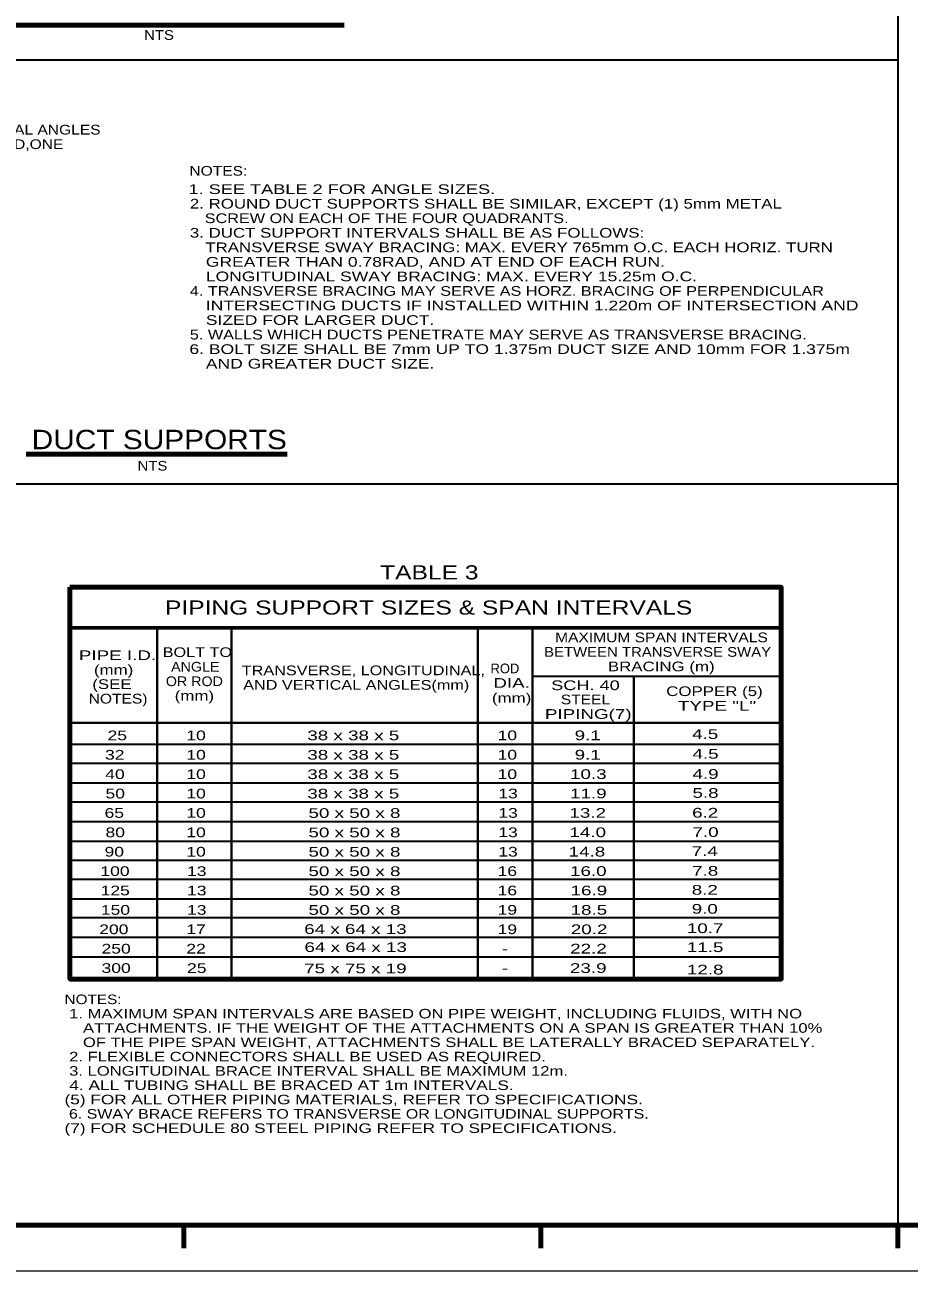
# Model space of a CAD drawing. Extents: x 55 to 190, y 198 to 264.
# Drawn here: x 117.13 to 140.29, y 198.45 to 231.1 of the extents above; entities that cross this region are included whole.
import ezdxf
from ezdxf.enums import TextEntityAlignment as Align

# ---------------------------------------------------------------- set-up
doc = ezdxf.new("R2010")
doc.units = 0
doc.header["$LTSCALE"] = 0.1
doc.layers.add('1', color=7, linetype='Continuous', lineweight=25)
doc.layers.add('2', color=7, linetype='Continuous', lineweight=40)

msp = doc.modelspace()

# ---------------------------------------------------------------- linework, layer by layer
at = {"layer": '1', "lineweight": 80}
for p, q in [((121.2927, 199.6512), (121.2927, 199.0512)), ((130.6427, 199.6512), (130.6427, 199.0512)), ((139.9927, 199.6512), (139.9927, 199.0512))]:
    msp.add_line(p, q, dxfattribs=at)
at = {"layer": '1', "lineweight": 13}
msp.add_lwpolyline([(62.4915, 257.8525), (146.5927, 257.8525), (146.5927, 198.4512), (62.4915, 198.4512)], close=True, dxfattribs=at)
at = {"layer": '1', "lineweight": 80}
msp.add_lwpolyline([(65.1915, 256.6525), (145.3927, 256.6525), (145.3927, 199.6512), (65.1915, 199.6512)], close=True, dxfattribs=at)
at = {"layer": '2', "lineweight": 35}
for p, q in [((139.9927, 256.6525), (139.9927, 199.6512)), ((102.5927, 230.1829), (139.9927, 230.1829)), ((102.5927, 219.0748), (139.9927, 219.0748)), ((130.4385, 214.0378), (136.9398, 214.0378)), ((118.3081, 212.2552), (136.9398, 212.2552)), ((118.3081, 211.753), (136.9398, 211.753)), ((118.3081, 211.2432), (136.9398, 211.2432)), ((118.3081, 210.741), (136.9398, 210.741)), ((118.3081, 210.2309), (136.9398, 210.2309)), ((118.3081, 209.7131), (136.9398, 209.7131)), ((118.3081, 209.2186), (136.9398, 209.2186)), ((118.3081, 208.7164), (136.9398, 208.7164)), ((118.3081, 208.1994), (136.9398, 208.1994)), ((118.3081, 207.7102), (136.9398, 207.7102)), ((118.3081, 207.1966), (136.9398, 207.1966)), ((118.3081, 206.6828), (136.9398, 206.6828))]:
    msp.add_line(p, q, dxfattribs=at)
at = {"layer": '2', "lineweight": 80}
for p, q in [((116.0467, 231.0941), (125.4958, 231.0941)), ((117.1647, 219.8485), (123.9978, 219.8485))]:
    msp.add_line(p, q, dxfattribs=at)
at = {"layer": '2', "lineweight": 60}
msp.add_line((136.9398, 215.3006), (118.3081, 215.3006), dxfattribs=at)
at = {"layer": '2'}
for p, q in [((120.5989, 215.3006), (120.5989, 206.092)), ((122.5412, 215.3006), (122.5393, 206.0923)), ((128.9946, 215.3006), (128.9946, 206.092)), ((130.4295, 215.3006), (130.4295, 206.0992)), ((133.078, 214.0378), (133.078, 206.0992)), ((118.3081, 212.8135), (136.9398, 212.8135))]:
    msp.add_line(p, q, dxfattribs=at)
at = {"layer": '2', "lineweight": 80}
msp.add_lwpolyline([(118.3081, 216.3645), (136.9398, 216.3645), (136.9398, 206.0992), (118.3081, 206.0992)], close=True, dxfattribs=at)

# ---------------------------------------------------------------- texts
at = {"layer": '1'}
for s, width, p in [('NOTES:', 1.2, (118.1687, 205.445)), (' 1. MAXIMUM SPAN INTERVALS ARE BASED ON PIPE WEIGHT, INCLUDING FLUIDS, WITH NO', 1.3, (118.1687, 205.07)), ('    ATTACHMENTS. IF THE WEIGHT OF THE ATTACHMENTS ON A SPAN IS GREATER THAN 10%', 1.3, (118.1687, 204.695)), ('    OF THE PIPE SPAN WEIGHT, ATTACHMENTS SHALL BE LATERALLY BRACED SEPARATELY.', 1.3, (118.1687, 204.32)), (' 2. FLEXIBLE CONNECTORS SHALL BE USED AS REQUIRED.', 1.3, (118.1687, 203.945)), (' 3. LONGITUDINAL BRACE INTERVAL SHALL BE MAXIMUM 12m.', 1.3, (118.1687, 203.57)), (' 4. ALL TUBING SHALL BE BRACED AT 1m INTERVALS.', 1.35, (118.1687, 203.195)), ('(5) FOR ALL OTHER PIPING MATERIALS, REFER TO SPECIFICATIONS.', 1.35, (118.1687, 202.82)), (' 6. SWAY BRACE REFERS TO TRANSVERSE OR LONGITUDINAL SUPPORTS.', 1.25, (118.1687, 202.445)), ('(7) FOR SCHEDULE 80 STEEL PIPING REFER TO SPECIFICATIONS.', 1.35, (118.1687, 202.07))]:
    msp.add_text(s, height=0.25, dxfattribs=dict(at, width=width)).set_placement(p)
at = {"layer": '2'}
for s, height, width, p in [('NTS', 0.254, 1.15, (120.6436, 230.7062)), ('DUCT SUPPORTS', 0.508, 1.15, (120.6508, 219.9821)), ('NTS', 0.254, 1.15, (120.472, 219.4214)), ('TABLE 3', 0.3704, 1.3, (127.7231, 216.5711)), ('PIPING SUPPORT SIZES & SPAN INTERVALS', 0.3704, 1.3, (127.7059, 215.6488)), ('MAXIMUM SPAN INTERVALS', 0.254, 1.2, (133.805, 214.9261)), ('PIPE I.D.', 0.254, 1.45, (119.5572, 214.4566)), ('BOLT TO', 0.254, 1.25, (121.6485, 214.5375)), ('BETWEEN TRANSVERSE SWAY', 0.254, 1.15, (133.7024, 214.5451)), ('(mm)', 0.254, 1.3, (119.4543, 214.0756)), ('ANGLE', 0.254, 1.1, (121.5943, 214.1565)), ('TRANSVERSE, LONGITUDINAL,', 0.254, 1.25, (125.9964, 214.0613)), ('BRACING (m)', 0.254, 1.3, (133.799, 214.1641)), ('(SEE', 0.254, 1.3, (119.4112, 213.7009)), ('OR ROD', 0.254, 1.1, (121.5699, 213.7755)), ('AND VERTICAL ANGLES(mm)', 0.254, 1.25, (125.8091, 213.6803)), ('DIA.', 0.254, 1.45, (129.8791, 213.7311)), ('SCH. 40', 0.254, 1.4, (131.8135, 213.6708)), ('NOTES)', 0.254, 1.2, (119.5715, 213.3199)), ('(mm)', 0.254, 1.3, (121.5699, 213.3978)), ('(mm)', 0.254, 1.3, (129.8791, 213.3396)), ('STEEL', 0.254, 1.2, (131.8135, 213.2991)), ('PIPING(7)', 0.254, 1.45, (131.886, 212.9181)), ('25', 0.254, 1.35, (119.5509, 212.3579)), ('10', 0.254, 1.35, (121.6143, 212.3579)), ('38 x 38 x 5', 0.254, 1.45, (125.7321, 212.3579)), ('10', 0.254, 1.35, (129.767, 212.3589)), ('9.1', 0.254, 1.45, (131.8723, 212.3595)), ('4.5', 0.254, 1.45, (134.9494, 212.392)), ('32', 0.254, 1.35, (119.4845, 211.8499)), ('10', 0.254, 1.35, (121.6143, 211.8499)), ('38 x 38 x 5', 0.254, 1.45, (125.7321, 211.8494)), ('10', 0.254, 1.35, (129.767, 211.8509)), ('9.1', 0.254, 1.45, (131.8723, 211.8515)), ('4.5', 0.254, 1.45, (134.9591, 211.8745)), ('40', 0.254, 1.35, (119.4903, 211.3419)), ('10', 0.254, 1.35, (121.6143, 211.3419)), ('38 x 38 x 5', 0.254, 1.45, (125.7321, 211.3411)), ('10', 0.254, 1.35, (129.767, 211.3429)), ('10.3', 0.254, 1.45, (131.8884, 211.3435)), ('4.9', 0.254, 1.45, (134.9581, 211.3469)), ('50', 0.254, 1.35, (119.4964, 210.8339)), ('10', 0.254, 1.35, (121.6143, 210.8339)), ('38 x 38 x 5', 0.254, 1.45, (125.7321, 210.8326)), ('13', 0.254, 1.35, (129.7852, 210.8349)), ('11.9', 0.254, 1.45, (131.8884, 210.8355)), ('5.8', 0.254, 1.45, (134.9581, 210.8492)), ('65', 0.254, 1.35, (119.4723, 210.3259)), ('10', 0.254, 1.35, (121.6143, 210.3259)), ('50 x 50 x 8', 0.254, 1.45, (125.7628, 210.324)), ('13', 0.254, 1.35, (129.7852, 210.3269)), ('13.2', 0.254, 1.45, (131.8725, 210.3275)), ('6.2', 0.254, 1.45, (134.9494, 210.3317)), ('80', 0.254, 1.35, (119.4964, 209.8179)), ('10', 0.254, 1.35, (121.6143, 209.8179)), ('50 x 50 x 8', 0.254, 1.45, (125.7628, 209.816)), ('13', 0.254, 1.35, (129.7852, 209.8189)), ('14.0', 0.254, 1.45, (131.8723, 209.8195)), ('7.0', 0.254, 1.45, (134.9591, 209.8242)), ('90', 0.254, 1.35, (119.4723, 209.3099)), ('10', 0.254, 1.35, (121.6143, 209.3099)), ('50 x 50 x 8', 0.254, 1.45, (125.7628, 209.308)), ('13', 0.254, 1.35, (129.7852, 209.3109)), ('14.8', 0.254, 1.45, (131.8514, 209.3115)), ('7.4', 0.254, 1.45, (134.9382, 209.3265)), ('100', 0.254, 1.35, (119.4903, 208.8019)), ('13', 0.254, 1.35, (121.6326, 208.8019)), ('50 x 50 x 8', 0.254, 1.45, (125.7628, 208.8)), ('16', 0.254, 1.35, (129.767, 208.8029)), ('16.0', 0.254, 1.45, (131.8884, 208.8035)), ('7.8', 0.254, 1.45, (134.9494, 208.809)), ('125', 0.254, 1.35, (119.4964, 208.2939)), ('13', 0.254, 1.35, (121.6326, 208.2939)), ('50 x 50 x 8', 0.254, 1.45, (125.7628, 208.292)), ('16', 0.254, 1.35, (129.767, 208.2949)), ('16.9', 0.254, 1.45, (131.9027, 208.2947)), ('8.2', 0.254, 1.45, (134.9382, 208.3116)), ('150', 0.254, 1.35, (119.5024, 207.7859)), ('13', 0.254, 1.35, (121.6326, 207.7859)), ('50 x 50 x 8', 0.254, 1.45, (125.7628, 207.784)), ('19', 0.254, 1.35, (129.767, 207.7869)), ('18.5', 0.254, 1.45, (131.9027, 207.7867)), ('9.0', 0.254, 1.45, (134.9382, 207.8139)), ('200', 0.254, 1.35, (119.4601, 207.2779)), ('17', 0.254, 1.35, (121.6143, 207.2779)), ('64 x 64 x 13', 0.254, 1.45, (125.7882, 207.2837)), ('19', 0.254, 1.35, (129.767, 207.2789)), ('20.2', 0.254, 1.45, (131.9088, 207.2787)), ('10.7', 0.254, 1.45, (134.948, 207.3065)), ('250', 0.254, 1.35, (119.5207, 206.7699)), ('22', 0.254, 1.35, (121.6143, 206.7699)), ('64 x 64 x 13', 0.254, 1.45, (125.7943, 206.8111)), ('22.2', 0.254, 1.45, (131.8926, 206.7707)), ('11.5', 0.254, 1.45, (134.948, 206.8088)), ('-', 0.254, 1.45, (129.7061, 206.7709)), ('300', 0.254, 1.35, (119.5207, 206.2619)), ('25', 0.254, 1.35, (121.6326, 206.2619)), ('75 x 75 x 19', 0.254, 1.45, (125.7876, 206.2526)), ('-', 0.254, 1.45, (129.7061, 206.2629)), ('23.9', 0.254, 1.45, (131.8865, 206.2627)), ('12.8', 0.254, 1.45, (134.9494, 206.2217))]:
    msp.add_text(s, height=height, dxfattribs=dict(at, width=width)).set_placement(p, align=Align.CENTER)
for s, width, p in [('LONGITUDINAL ANGLES', 1.2, (114.3335, 228.2262)), ('AS REQUIRED,ONE', 1.2, (114.3335, 227.8452)), ('NOTES:', 1.2, (121.4394, 227.1481)), ('1. SEE TABLE 2 FOR ANGLE SIZES.', 1.4, (121.4151, 226.6677)), ('2. ROUND DUCT SUPPORTS SHALL BE SIMILAR, EXCEPT (1) 5mm METAL ', 1.3, (121.4513, 226.2867)), ('   SCREW ON EACH OF THE FOUR QUADRANTS.', 1.25, (121.4876, 225.9057)), ('3. DUCT SUPPORT INTERVALS SHALL BE AS FOLLOWS:', 1.3, (121.4513, 225.5247)), ('   TRANSVERSE SWAY BRACING: MAX. EVERY 765mm O.C. EACH HORIZ. TURN', 1.3, (121.4876, 225.1436)), ('   GREATER THAN 0.78RAD, AND AT END OF EACH RUN.', 1.35, (121.4876, 224.7627)), ('   LONGITUDINAL SWAY BRACING: MAX. EVERY 15.25m O.C.', 1.35, (121.4876, 224.3817)), ('4. TRANSVERSE BRACING MAY SERVE AS HORZ. BRACING OF PERPENDICULAR', 1.25, (121.4513, 224.0006)), ('   INTERSECTING DUCTS IF INSTALLED WITHIN 1.220m OF INTERSECTION AND', 1.35, (121.4876, 223.6197)), ('   SIZED FOR LARGER DUCT.', 1.35, (121.4876, 223.2387)), ('5. WALLS WHICH DUCTS PENETRATE MAY SERVE AS TRANSVERSE BRACING.', 1.25, (121.4513, 222.8576)), ('6. BOLT SIZE SHALL BE 7mm UP TO 1.375m DUCT SIZE AND 10mm FOR 1.375m', 1.35, (121.4394, 222.4767)), ('   AND GREATER DUCT SIZE.', 1.35, (121.4876, 222.0957)), ('COPPER (5)', 1.3, (133.9291, 213.5153)), ('TYPE "L"', 1.45, (134.2361, 213.1343))]:
    msp.add_text(s, height=0.254, dxfattribs=dict(at, width=width)).set_placement(p)
msp.add_text('ROD', height=0.254, dxfattribs=at).set_placement((129.7037, 214.1121), align=Align.CENTER)

doc.saveas('drawing.dxf')
